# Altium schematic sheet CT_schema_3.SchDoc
size 310 x 315 mm
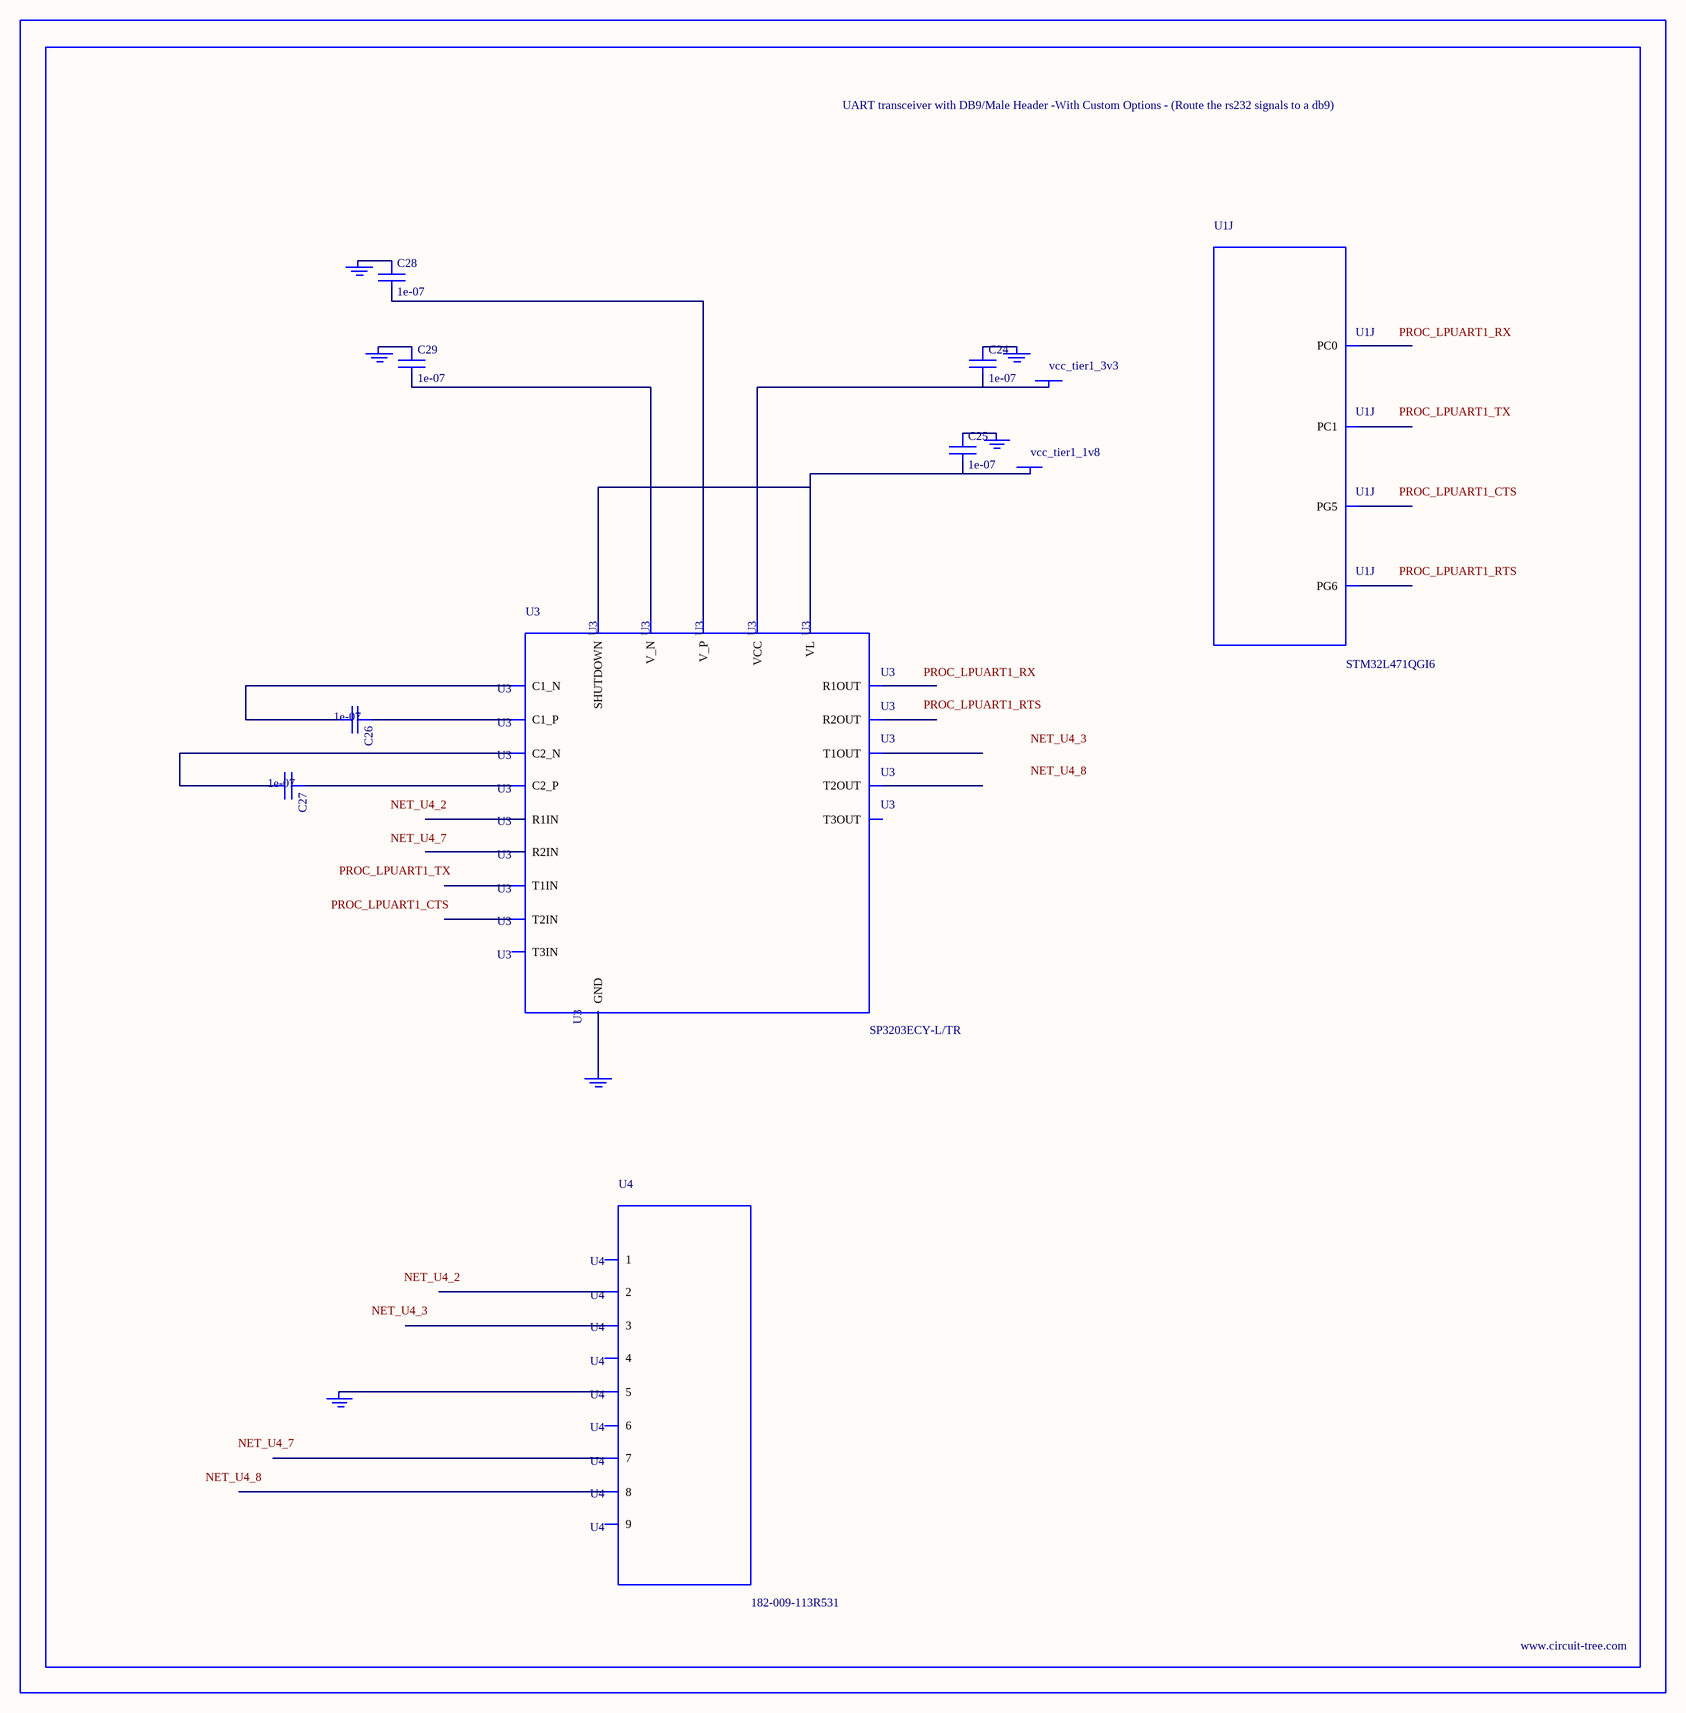
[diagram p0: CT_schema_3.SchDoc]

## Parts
BORDER2  (no value)
C24  1e-07  [C0402]
C25  1e-07  [C0402]
C26  1e-07  [C0402]
C27  1e-07  [C0402]
C28  1e-07  [C0402]
C29  1e-07  [C0402]
GND_INSTANCE_2_0  (no value)
GND_INSTANCE_2_1  (no value)
GND_INSTANCE_2_2  (no value)
GND_INSTANCE_2_3  (no value)
GND_INSTANCE_2_4  (no value)
GND_INSTANCE_2_5  (no value)
POWER_INSTANCE_2_0  vcc_tier1_1v8
POWER_INSTANCE_2_1  vcc_tier1_3v3
U1  STM32L471QGI6  [UFBGA132]  (part J of 12)
U3  SP3203ECY-L/TR  [TSSOP20-I]
U4  182-009-113R531  [182-009-MALE]

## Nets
NetC24_1: C24.1 GND_INSTANCE_2_3.0(GND)
NetC24_2: C24.2 POWER_INSTANCE_2_1.0(PWR) U3.19(VCC)
NetC25_1: C25.1 GND_INSTANCE_2_2.0(GND)
NetC25_2: C25.2 POWER_INSTANCE_2_0.0(PWR) U3.12(VL) U3.20(SHUTDOWN)
NetC26_1: C26.1 U3.1(C1_P)
NetC26_2: C26.2 U3.3(C1_N)
NetC27_1: C27.1 U3.4(C2_P)
NetC27_2: C27.2 U3.5(C2_N)
NetC28_1: C28.1 GND_INSTANCE_2_0.0(GND)
NetC28_2: C28.2 U3.2(V_P)
NetC29_1: C29.1 GND_INSTANCE_2_1.0(GND)
NetC29_2: C29.2 U3.6(V_N)
NetGND_INSTANCE_2_4_0: GND_INSTANCE_2_4.0(GND) U3.18(GND)
NetGND_INSTANCE_2_5_0: GND_INSTANCE_2_5.0(GND) U4.5

Not connected (* = marked no-connect by the designer): U1 E9(PG5) G4(PG6) H1(PC0) J2(PC1); U3 7(T1IN) 8(T2IN) 9(T3IN) 10(R2OUT) 11(R1OUT) 13(R2IN) 14(R1IN) 15(T3OUT) 16(T2OUT) 17(T1OUT); U4 1 2 3 4 6 7 8 9

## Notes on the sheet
- Labels drawn without touching a wire or pin: NET_U4_2, NET_U4_3, NET_U4_7, NET_U4_8, PROC_LPUART1_CTS, PROC_LPUART1_RTS, PROC_LPUART1_RX, PROC_LPUART1_TX

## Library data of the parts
BORDER2 = BORDER_PAGE2
C24-C29 = C0402C104K3RACTU
GND_INSTANCE_2_0-GND_INSTANCE_2_5 = GND
POWER_INSTANCE_2_0 POWER_INSTANCE_2_1 = PWR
